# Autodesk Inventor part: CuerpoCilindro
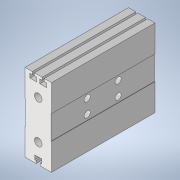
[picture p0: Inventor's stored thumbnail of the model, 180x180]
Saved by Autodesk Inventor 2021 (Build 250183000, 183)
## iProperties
Created: 2021-02
Part Number: CuerpoCilindro
Material: Genérico
Document SubType Name: Modeling
Designer: ATOUZA
Density: 1 g/cm^3
Appearance: Valor por defecto
Author: ATOUZA
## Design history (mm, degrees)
sketch "Boceto1"
  geometry: L1 (-17.125, -50.2)-(17.125, 50.2); L2 (17.125, -50.2)-(-17.125, 50.2); L3 (-2.8, -50.2)-(-2.8, -46.8); L4 (-2.8, -46.8)-(-4.5, -46.8); L5 (-4.5, -46.8)-(-4.5, -41.4); L6 (-4.5, -41.4)-(0, -41.4); L7 (0, -50.2)-(0, 50.2); L8 (2.8, -50.2)-(2.8, -46.8); L9 (2.8, -46.8)-(4.5, -46.8); L10 (4.5, -46.8)-(4.5, -41.4); L11 (4.5, -41.4)-(0, -41.4); L12 (-17.125, -50.2)-(-2.8, -50.2); L13 (2.8, -50.2)-(17.125, -50.2); L14 (-7.8, 50.2)-(-7.8, 46.8); L15 (-7.8, 46.8)-(-10.9, 46.8); L16 (-10.9, 46.8)-(-10.9, 41.4); L17 (-10.9, 41.4)-(-1.9, 41.4); L18 (-1.9, 41.4)-(-1.9, 46.8); L19 (-1.9, 46.8)-(-5, 46.8); L20 (-5, 46.8)-(-5, 50.2); L21 (10.9, 46.8)-(10.9, 41.4); L22 (10.9, 41.4)-(1.9, 41.4); L23 (1.9, 41.4)-(1.9, 46.8); L24 (1.9, 46.8)-(5, 46.8); L25 (5, 46.8)-(5, 50.2); L26 (7.8, 50.2)-(7.8, 46.8); L27 (7.8, 46.8)-(10.9, 46.8); L28 (-7.8, 50.2)-(-17.125, 50.2); L29 (17.125, 50.2)-(7.8, 50.2); L30 (5, 50.2)-(-5, 50.2); L31 (-17.125, 0)-(17.125, 0); L32 (-17.125, -15.5)-(-16.625, -15.5); L33 (-16.625, -15.5)-(-16.625, 15.5); L34 (-16.625, 15.5)-(-17.125, 15.5); L35 (-17.125, 50.2)-(-17.125, 15.5); L36 (-17.125, -15.5)-(-17.125, -50.2); L37 (16.625, -15.5)-(16.625, 15.5); L38 (17.125, -15.5)-(16.625, -15.5); L39 (16.625, 15.5)-(17.125, 15.5); L40 (17.125, -50.2)-(17.125, -15.5); L41 (17.125, 15.5)-(17.125, 50.2); C1 r 5 at (0, -25); C2 r 5 at (0, 25); 1 further point
  constraints: 82 end point, 17 perpendicular, 17 symmetric about line, 10 parallel, 6 point on line, 3 horizontal, 3 midpoint, 3 vertical, 2 centre point, 1 other
  dimensions: "d0" = 34.25 distance of L2.end L1.end; "d1" = 100.4 distance of L1.end L2.start; "d2" = 2.8 distance between parallel lines of L3 L7; "d3" = 4.5 distance between parallel lines of L5 L7; "d5" = 5.4 distance between parallel lines of L6 L4; "d6" = 3.4 distance of L3.start L3.end; "d8" = 5.4 distance between parallel lines of L17 L15; "d9" = 9 distance of L16.end L17.end; "d10" = 2.8 distance between parallel lines of L14 L20; "d11" = 3.1 distance between parallel lines of L20 L18; "d12" = 5 distance between parallel lines of L7 L20; "d13" = 10 diameter of C1; "d14" = 25 distance of point (0, 0) C1.centre; "d15" = 31 distance between parallel lines of L32 L34; "d16" = 15.5 distance between parallel lines of L31 L34
extrude "Extrusión1" new body sketch "Boceto1" distance "d18" = 133.75; taper "d19" = 0 deg
sketch "Boceto2"
  geometry: L1 (0, 15.5)-(-133.75, 15.5); L2 (-133.75, 31)-(-133.75, 0) reference; L3 (0, -34.7)-(0, 0) reference; L4 (0, 0)-(0, 31) reference; L5 (0, 0)-(0, 31); C1 r 4 at (-47.25, 24.5); C2 r 4 at (-87.25, 24.5); C3 r 4 at (-87.25, 6.5); C4 r 4 at (-47.25, 6.5)
  constraints: 4 centre point, 4 end point, 2 midpoint, 2 symmetric about line, 1 collinear, 2 other
  dimensions: "d20" = 8 diameter of C1; "d21" = 9 distance from line of L1 C1.centre; "d22" = 8 diameter of C2; "d23" = 40 distance of C1.centre C2.centre; "d24" = 47.25 distance from line of L4 C1.centre; "d29" = 9 distance from line of L1 C2.centre
extrude "Extrusión2" cut sketch "Boceto2" extent not by distance; stored distance "d25" = 0.5; taper "d26" = 0 deg
node "Sólido1"
other parameters: "d4" = 3.4, "d7" = 3.4, "d17" = 0.5
